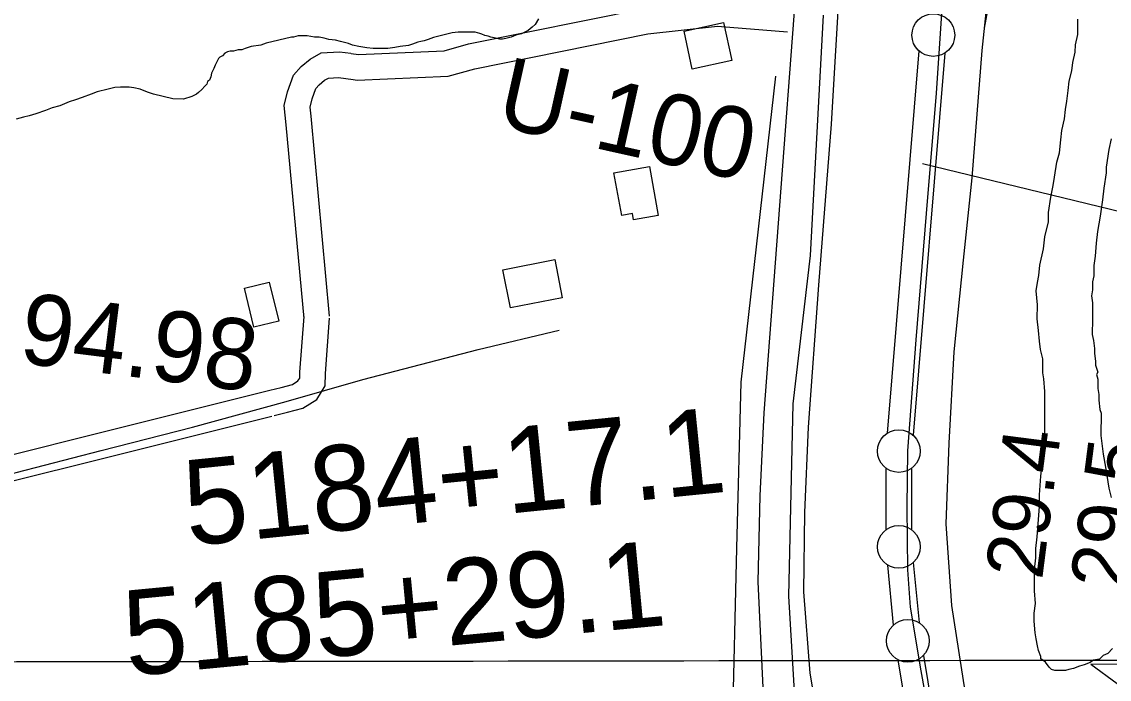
# Model space of a CAD drawing. Extents: x 3324125 to 3362000, y 600753 to 626151.
# Drawn here: x 3331432 to 3332706, y 618241 to 619010 of the extents above; entities that cross this region are included whole.
import ezdxf

# ---------------------------------------------------------------- set-up
doc = ezdxf.new("R2010")
doc.units = 0
for name, color, linetype in [('V-BLDG-OTLN', 7, 'Continuous'), ('V-CHAN-NAID', 7, 'Continuous'), ('V-DTCH-CNTR', 7, 'Continuous'), ('V-FLOD-BASE', 7, 'Continuous'), ('V-GRID-MAJR', 7, 'Continuous'), ('V-LEVE-TOET', 7, 'Continuous'), ('V-RIVR-RANG', 7, 'Continuous'), ('V-RIVR-RANG-IDEN', 7, 'Continuous'), ('V-ROAD-CNTR', 7, 'Continuous'), ('V-SITE-VEGE', 7, 'Continuous'), ('V-SURV-IDEN', 7, 'Continuous'), ('V-SURV-LINE', 7, 'Continuous'), ('V-TOPO-MINR', 7, 'Continuous'), ('V-TOPO-SHOR', 7, 'Continuous')]:
    doc.layers.add(name, color=color, linetype=linetype)

msp = doc.modelspace()

# ---------------------------------------------------------------- linework, layer by layer
at = {"layer": 'V-BLDG-OTLN'}
for points in [[(3332254.2, 619009.6), (3332263.9, 618964.8), (3332217.6, 618954.8), (3332207.9, 618999.5)], [(3332125.9, 618833.6), (3332167.4, 618841.1), (3332177.8, 618783.7), (3332148.7, 618778.5), (3332147.4, 618785.8), (3332134.9, 618783.6)], [(3332056.5, 618732), (3332065.3, 618687.3), (3332004.6, 618675.3), (3331995.8, 618720)], [(3331693.1, 618698.3), (3331722.3, 618705.4), (3331733.4, 618659.8), (3331704.2, 618652.7)]]:
    msp.add_lwpolyline(points, close=True, dxfattribs=at)
at = {"layer": 'V-CHAN-NAID'}
msp.add_lwpolyline([(3332760.7, 618257.8), (3332684.2, 618258.3), (3332745.8, 618212.9)], dxfattribs=at)
at = {"layer": 'V-DTCH-CNTR'}
msp.add_lwpolyline([(3331215.2, 618426.9), (3331311.8, 618453.3), (3331425.9, 618482.8), (3331525.6, 618508.5), (3331632.5, 618535.7), (3331741.9, 618566), (3331832, 618591.7), (3331966.9, 618626.7), (3332061.8, 618649.2)], dxfattribs=at)
at = {"layer": 'V-FLOD-BASE'}
msp.add_lwpolyline([(3332601.3, 620273.8), (3332592.4, 620148.9), (3332587.7, 620067.3), (3332576.9, 619927.9), (3332564.9, 619779.7), (3332557.8, 619673), (3332548.2, 619552.8), (3332541.2, 619452.5), (3332532.7, 619322.4), (3332523.3, 619214.5), (3332513.7, 619084.4), (3332503.3, 618926.9), (3332491.3, 618785.8), (3332479.3, 618638.2), (3332469.7, 618508.2), (3332468.7, 618442.2), (3332469.4, 618368.7), (3332472.6, 618324.9), (3332485, 618250.7), (3332512, 618101.1)], dxfattribs=at)
at = {"layer": 'V-GRID-MAJR'}
msp.add_spline([(3328217.9, 618256.9), (3333482.8, 618264.2), (3338747.8, 618272.2), (3344012.7, 618281.1), (3349277.7, 618290.6), (3354542.6, 618301), (3359807.6, 618312.1)], degree=3, dxfattribs=at)
at = {"layer": 'V-LEVE-TOET'}
for points in [[(3332544.6, 618179.1), (3332532.3, 618256.8), (3332521.6, 618326.9), (3332514.7, 618422.7), (3332518.2, 618517.2), (3332524.2, 618623.9), (3332535.3, 618731.2), (3332545.3, 618827.5), (3332556.8, 618976.8), (3332569.2, 619091.7), (3332580.5, 619215.9), (3332589.8, 619385.1), (3332600.7, 619540.2), (3332608.5, 619659.2), (3332620.6, 619816.7), (3332632, 619955.5), (3332644.7, 620125.8), (3332661.5, 620282.7)], [(3332465.8, 620256.5), (3332452.4, 620072.8), (3332441.8, 619879.1), (3332437.9, 619728.6), (3332431.2, 619600.3), (3332422.7, 619454.4), (3332408, 619247.3), (3332390.4, 619063.1), (3332380, 618890.4), (3332365.3, 618702), (3332353.2, 618535.8), (3332349, 618436), (3332347.9, 618343.2), (3332355.4, 618248), (3332368.3, 618169.8)]]:
    msp.add_lwpolyline(points, dxfattribs=at)
at = {"layer": 'V-RIVR-RANG'}
msp.add_line((3332487, 618844.6), (3333517, 618594.1), dxfattribs=at)
at = {"layer": 'V-ROAD-CNTR'}
for points in [[(3332435.8, 620389.6), (3332374.7, 619523.7), (3332301.3, 618552.7), (3332296.7, 618455.5), (3332294.2, 618354.6), (3332300.5, 618222.7), (3332312.6, 617992.5), (3332321.2, 617895.8), (3332318.6, 617826.1), (3332311.6, 617761.4), (3332293.4, 617690.8), (3332279.8, 617637.3), (3332250, 617572.9), (3332125.9, 617304.4), (3332097.6, 617233.7), (3332075.6, 617180.9), (3332062.2, 617134.3), (3332055.9, 617103.1), (3332053.1, 617059.6), (3332049, 617007.9), (3332050.3, 616945.8), (3332056, 616867)], [(3331818.3, 618973.3), (3331826.6, 618972.2), (3331927.1, 618976.4), (3331955.7, 618984.5), (3332161.1, 619026), (3332246.9, 619035.2), (3332331.4, 619028.3)], [(3331820.7, 618942.7), (3331825.1, 618942.1), (3331931.9, 618946.6), (3331962.8, 618955.3), (3332165.7, 618996.3), (3332247.2, 619005.1), (3332328.9, 618998.4)], [(3331742, 618889.5), (3331739.9, 618912.2), (3331743.6, 618928.5), (3331750.8, 618948), (3331759.7, 618958), (3331770, 618966.7), (3331783.1, 618973.9), (3331804.7, 618975.3), (3331817.9, 618973.4)], [(3331771.2, 618899.8), (3331770.2, 618910.3), (3331772.4, 618920), (3331776.9, 618932.2), (3331780.7, 618936.5), (3331787.1, 618941.9), (3331791.6, 618944.4), (3331803.5, 618945.1), (3331820.7, 618942.7)], [(3331793, 618665.8), (3331771.2, 618899.8)], [(3331763.1, 618663), (3331742, 618889.5)], [(3331723.1, 618579.1), (3331736.2, 618582.4), (3331749.6, 618585.8), (3331755.9, 618589.9), (3331758, 618593.2), (3331758.1, 618600), (3331763.1, 618665.5)], [(3331727.9, 618549.4), (3331743.5, 618553.3), (3331761.7, 618557.9), (3331777.8, 618568.3), (3331787.8, 618584.2), (3331788.1, 618598.6), (3331793, 618663.2)], [(3331214, 618452), (3331723.1, 618579.1)], [(3331220.1, 618422.6), (3331725.4, 618548.8)]]:
    msp.add_lwpolyline(points, dxfattribs=at)
at = {"layer": 'V-SITE-VEGE'}
for points in [[(3332037.5, 619013.6), (3332033.5, 619007.2), (3332030.3, 619004.1), (3332025.5, 619000.1), (3332017.5, 618996.2), (3332011.1, 618994.6), (3332005.5, 618992.3), (3331999.2, 618990.7), (3331995.2, 618990), (3331992, 618990), (3331985.6, 618991.6), (3331981.7, 618992.4), (3331978.5, 618993.3), (3331974.5, 618994.1), (3331971.3, 618995.7), (3331968.9, 618996.5), (3331963.4, 618998.1), (3331943.5, 618998.3), (3331936.3, 618997.5), (3331914.7, 618992.1), (3331908.4, 618989.7), (3331903.6, 618988.2), (3331899.6, 618987.4), (3331896.4, 618986.6), (3331890, 618984.3), (3331885.2, 618982.7), (3331875.6, 618981.2), (3331869.3, 618980.4), (3331861.3, 618978.9), (3331843.8, 618979), (3331836.6, 618979.8), (3331827.1, 618981.5), (3331819.9, 618983.1), (3331815.1, 618984.8), (3331805.6, 618987.2), (3331800, 618988.8), (3331792.1, 618989.7), (3331786.5, 618991.3), (3331780.9, 618992.2), (3331775.4, 618992.2), (3331766.6, 618993.8), (3331756.2, 618993.9), (3331750.7, 618992.3), (3331748.3, 618992.4), (3331718.8, 618985.4)], [(3332631.2, 618260.5), (3332625.8, 618264.7), (3332625.8, 618267.4), (3332623.1, 618274.3), (3332621.8, 618279.8), (3332620.4, 618288), (3332619.1, 618294.9), (3332617.8, 618308.6), (3332617.9, 618318.2), (3332619.3, 618329.2), (3332618.1, 618344.3), (3332618.2, 618369), (3332619.7, 618382.7), (3332619.8, 618393.6), (3332621.2, 618407.3), (3332624.2, 618443), (3332624.3, 618456.7), (3332625.8, 618478.6), (3332627.2, 618492.4), (3332628.8, 618518.4), (3332630.2, 618526.6), (3332630.4, 618548.6), (3332630.5, 618577.4), (3332629.3, 618592.5), (3332627.9, 618599.3), (3332628, 618615.8), (3332625.4, 618626.8), (3332624.1, 618636.4), (3332622.8, 618648.8), (3332621.5, 618662.5), (3332621.6, 618678.9), (3332620.3, 618695.4), (3332621.8, 618705), (3332623.2, 618713.2), (3332624.6, 618725.6), (3332628.9, 618744.7), (3332630.3, 618758.4), (3332634.6, 618776.2), (3332634.6, 618787.2), (3332637.5, 618805), (3332640.3, 618818.7), (3332641.8, 618828.3), (3332644.6, 618846.1), (3332647.4, 618857.1), (3332648.9, 618872.2), (3332650.4, 618883.1), (3332653.2, 618896.8), (3332654.6, 618907.8), (3332656.1, 618917.4), (3332657.5, 618929.7), (3332659, 618940.7), (3332661.8, 618953), (3332663.2, 618962.6), (3332666, 618974.9), (3332666.1, 618983.2), (3332668.9, 618995.5), (3332669, 619013.3)], [(3331718.8, 618985.4), (3331712.4, 618983), (3331701.2, 618981.5), (3331694, 618979.2), (3331690, 618977.6), (3331686, 618977.6), (3331680.5, 618976.1), (3331676.5, 618976.1), (3331673.3, 618975.3), (3331670.1, 618973.7), (3331667.7, 618970.6), (3331664.5, 618969), (3331662.9, 618967.4), (3331658.8, 618959.5), (3331657.2, 618955.5), (3331656.4, 618953.1), (3331654.8, 618950), (3331654, 618946), (3331652.4, 618942), (3331650, 618940.4), (3331649.1, 618937.2), (3331646.7, 618934.9), (3331643.5, 618930.9), (3331639.5, 618927.7), (3331637.1, 618925.4), (3331631.5, 618923), (3331621.9, 618919.9), (3331609.2, 618920), (3331586.9, 618925.7), (3331579.8, 618928.1), (3331571, 618931.4), (3331563.9, 618933), (3331558.3, 618933.8), (3331548, 618933.9), (3331541.6, 618933.2), (3331533.6, 618931.6), (3331520.8, 618928.5), (3331513.7, 618925.4), (3331503.3, 618921.5), (3331495.3, 618919.1), (3331488.1, 618916.8), (3331476.9, 618912.1), (3331468.2, 618909.7), (3331460.2, 618906.6), (3331449, 618902.7), (3331441, 618900.4), (3331434.6, 618898.8), (3331425.9, 618896.5)], [(3332707.9, 618873.2), (3332705.1, 618860.8), (3332702.2, 618840.3), (3332702.2, 618833.4), (3332699.3, 618815.6), (3332697.8, 618801.9), (3332695, 618782.7), (3332692.1, 618764.9), (3332690.6, 618751.2), (3332689.2, 618736.1), (3332687.7, 618725.2), (3332687.7, 618712.8), (3332686.2, 618706), (3332686.2, 618696.4), (3332684.8, 618689.5), (3332686.1, 618681.3), (3332686, 618662.1), (3332685.8, 618644.2), (3332687.2, 618637.4), (3332688.5, 618627.8), (3332688.4, 618622.3), (3332689.8, 618612.7), (3332689.7, 618608.5), (3332692.4, 618600.3), (3332691, 618597.6), (3332692.4, 618592.1), (3332692.3, 618581.1), (3332693.6, 618574.2), (3332693.6, 618567.4), (3332694.9, 618556.4), (3332696.2, 618552.3), (3332696.1, 618526.2), (3332698.7, 618504.2), (3332701.3, 618489.1), (3332705.3, 618464.4), (3332707.9, 618453.4)], [(3332709.5, 618276.5), (3332704, 618271), (3332698.5, 618268.3), (3332694.4, 618264.2), (3332687.5, 618262.9), (3332683.4, 618260.2), (3332676.5, 618257.5), (3332671, 618256.1), (3332664.1, 618253.4), (3332658.6, 618252.1), (3332654.5, 618250.8), (3332642.2, 618250.8), (3332638, 618252.2), (3332635.3, 618255), (3332631.2, 618260.5)]]:
    msp.add_lwpolyline(points, dxfattribs=at)
at = {"layer": 'V-SURV-LINE'}
for points in [[(3332446.1, 618528.9), (3332483.2, 618976.2)], [(3332513.1, 618973.7), (3332476, 618526.4)], [(3332444.4, 618415.7), (3332444.4, 618487.8)], [(3332474.4, 618487.8), (3332474.4, 618415.7)], [(3332453.2, 618304.1), (3332446.4, 618374.4)], [(3332476.3, 618377.3), (3332483.1, 618307)], [(3332479.1, 618140.3), (3332458.5, 618263.5)], [(3332488.1, 618268.5), (3332508.7, 618145.3)]]:
    msp.add_lwpolyline(points, dxfattribs=at)
for centre in [(3332499.8, 618994.8), (3332459.4, 618507.8), (3332459.4, 618395.7), (3332470, 618285.7)]:
    msp.add_circle(centre, 25, dxfattribs=at)
at = {"layer": 'V-TOPO-MINR'}
msp.add_lwpolyline([(3332833.8, 620009.2), (3332673.1, 619606.4), (3332666.1, 619587.1), (3332659.9, 619567.5), (3332655, 619547.5), (3332651, 619527.3), (3332623.7, 619363.3), (3332613.6, 619303.2), (3332603.2, 619243), (3332592.5, 619182.9), (3332581.6, 619122.9), (3332559.4, 619002.9)], dxfattribs=at)
at = {"layer": 'V-TOPO-SHOR'}
for points in [[(3332361.2, 617877.9), (3332351, 617985.2), (3332345.9, 618082.4), (3332330.5, 618338.1), (3332335.6, 618563.1), (3332356.1, 618736.9), (3332371.4, 619018.2)], [(3332315.2, 618946.6), (3332274.3, 618588.6), (3332269.2, 618394.3), (3332264.1, 618179.6), (3332284.5, 617975), (3332294.7, 617842.1), (3332294.7, 617790.9), (3332269.2, 617693.8), (3332197.6, 617525), (3332059.5, 617197.8), (3332028.8, 617080.2), (3332018.6, 616977.9), (3332018.6, 616896.1)]]:
    msp.add_lwpolyline(points, dxfattribs=at)

# ---------------------------------------------------------------- texts
at = {"layer": 'V-RIVR-RANG'}
for s, p in [('29.4', (3332627.1, 618356.1)), ('29.5', (3332726.3, 618343.6))]:
    msp.add_text(s, height=67, rotation=82.6983, dxfattribs=at).set_placement(p)
at = {"layer": 'V-RIVR-RANG-IDEN'}
for s, rotation, p in [('U-100', 347.4136, (3331985.5, 618888.9)), ('R-194.98', 352.8427, (3331250.1, 618633.8))]:
    msp.add_text(s, height=83, rotation=rotation, dxfattribs=at).set_placement(p)
at = {"layer": 'V-SURV-IDEN'}
for s, rotation, p in [('5184+17.1', 5.7586, (3331627.3, 618396.6)), ('5185+29.1', 5.4303, (3331556.3, 618244.1))]:
    msp.add_text(s, height=100, rotation=rotation, dxfattribs=at).set_placement(p)

doc.saveas('drawing.dxf')
